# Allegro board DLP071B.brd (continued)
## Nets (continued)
SWNODE2_P2P5V: D2.1(C) L3.1 U2.41
SWNODE_CORE: D501.1(C) L6.1 Q2.3(S) U15.25
SWNODE_MOT: D6.1(C) L7.2 U15.10
SWNODE_MOT2: D3.1(C) L2.2 U2.10
SWNODE_P2P5V: D7.1(C) L9.1 U15.41
SWNODE_P3P3V: D8.1(C) L8.1 U15.43
SWNODE_P5V: D4.1(C) L5.2 U15.23
TCK: J23.9 J27.15 J42.5 R710.1 U11.N24
TDI: J23.5 J27.19 J42.2 R716.1 U11.N25
TDO1: J42.4 U11.N23
TDO2: J23.13 J27.11 R708.1 U11.N22
TILT_X: R514.2 U3.5
TILT_Y: R14.2 U3.2
TMS1: J42.3 U11.P25
TMS2: J23.7 J27.17 R715.1 U11.P26
TRACECLK: J27.6 RN504.12
TRACECLKR: RN504.5 U11.D7
TRACEPKT0: J27.30 J28.1 R641.2 RN505.9
TRACEPKT0R: RN505.8 U11.C2
TRACEPKT1: J27.28 J28.2 R640.2 RN505.10
TRACEPKT1R: RN505.7 U11.D3
TRACEPKT2: J27.26 J28.3 R639.2 RN505.11
TRACEPKT2R: RN505.6 U11.E6
TRACEPKT3: J27.24 J28.4 R638.2 RN505.12
TRACEPKT3R: RN505.5 U11.D5
TRACEPKT4: J27.22 J28.5 R637.2 RN505.13
TRACEPKT4R: RN505.4 U11.E7
TRACEPKT5: J27.20 J28.6 RN505.14
TRACEPKT5R: RN505.3 U11.C4
TRACEPKT6: J27.18 J28.7 RN505.15
TRACEPKT6R: RN505.2 U11.B4
TRACEPKT7: J27.16 J28.8 RN505.16
TRACEPKT7R: RN505.1 U11.E8
TRACESYNC: J27.32 RN504.13
TRACESYNCR: RN504.4 U11.A5
TRSTZ: J27.21 R723.1 U11.M23 U514.4
TRSTZ_IN: J23.3 J42.1 R717.1 R724.2 U514.1
UART0_CTSZ: U6.12 U9.2
UART0_CTSZ_BUF: U9.6 U11.AE2
UART0_CTSZ_CON: J7.7 U6.13
UART0_DCD_CON: J7.1 R18.1
UART0_DSR_CON: J7.6 R18.2 R19.2
UART0_DTR_CON: J7.4 R19.1
UART0_RSTZ_CON: J7.8 U6.14
UART0_RTSZ: U10.5 U11.AD2
UART0_RTSZ_BUF: R534.2 R591.1 U6.11 U10.3
UART0_RXD: R589.1 U6.9 U9.5
UART0_RXD_BUF: U9.3 U11.AD1
UART0_RXD_CON: J7.3(TD) U6.8
UART0_TXD: U10.2 U11.AB3
UART0_TXD_BUF: R535.1 U6.10 U10.6
UART0_TXD_CON: J7.2 U6.7
UART1_CTSZ: U11.E18 U12.12
UART1_CTSZ_CON: J16.7 U12.13
UART1_DCD_CON: J16.1 R29.1
UART1_DSR_CON: J16.6 R29.2 R30.2
UART1_DTR_CON: J16.4 R30.1
UART1_RSTZ_CON: J16.8 U12.14
UART1_RTSZ: R573.2 U11.A19 U12.11
UART1_RXD: J2.92 U11.D19 U12.9
UART1_RXD_CON: J16.3(TD) U12.8
UART1_TXD: J2.53 R34.1 U11.C19 U12.10
UART1_TXD_CON: J16.2 U12.7
USB_DAT_N: J4.2 R518.1 U502.6
USB_DAT_NS: DN504.1 R518.2 U11.C5
USB_DAT_P: J4.3 R519.1 R531.1 U502.1
USB_DAT_PS: DN504.2 R519.2 U11.D6
USB_ENZ: R530.1 U11.E25 U503.1
XTAL_IN: C532.1 R556.1 R557.2 U11.M26 X500.1
XTAL_OUT: R555.2 R556.2 U11.N26
N16773791: J2.1 R2.2
N16781966: J1.92 R9.2 R10.2
N16804199: D11.2(CATHODE) R699.1
N16826457: Q4.3 R699.2
N16826574: Q3.3 Q4.2 R691.2
N16826732: Q503.3 R711.1
N16826745: Q3.2 R692.2
N16826772: J17.1 R607.2
N16826808: C36.2 Q5.1 R45.1 R711.2
N16827011: C531.1 R555.1 X500.2
N16827097: Q503.2 R574.2
N16827292: R650.1 U15.1
N16827323: R46.2 R60.1 U17.4
N16827429: D9.1 R700.2
N16827460: R47.2 U17.1
N16827499: D11.1 R701.2
N16827743: D10.1 R48.2
N16830133: R666.1 R667.1 U509.1 U509.3 U509.11
N16830205: C634.1 R660.1 R661.2 U15.30 U509.4
N16830232: Q2.2 Q2.4 R611.1 U15.28
N16830236: D5.2 L6.2
N16830344: C642.2 C643.2 Q505.3(S) R659.2 R662.2 R702.2
N16830356: R616.1 U507.6
N16830372: D5.1(K) R35.1
N16830397: R617.2 U507.5
N16830529: R614.1 R615.1 U507.1 U507.2 U507.3
N16830564: R664.1 U509.6
N16830576: C642.1 R652.2 R659.1 U15.32 U509.14(W3)
N16830606: Q505.1 U15.33
N16830689: R662.1 U509.12
N16830707: R663.2 U509.13
N16830891: R665.2 U509.5
N16832566: C26.2 L7.1 R33.1
N16836092: C669.2 J59.1 L505.1 R749.1 R770.2
N16836211: R751.2 TP62.1 U519.3 VR2.2(WIPER)
N16862598: J48.3 R776.2 R777.2
N16862628: Q504.2 R668.1
N16862652: R622.2 U508.4
N16862691: R778.2 U524.4
N16862716: C676.2 R765.2 R766.2 U524.5(VCC)
N16862889: C612.2 R618.2 R620.2 U508.5(VCC)
N16862891: J34.2 Q504.3 R669.2
N16869658: J5.1 R1.2 U4.1
N16869662: R11.2 U4.55 U4.56
N16888382: J47.1 J47.8 R726.1
N16888389: J47.13 R742.1
N16888395: J47.11 R725.1
N16888418: J47.12 R741.1
N16906032: C25.1 U12.2
N16906053: C24.1 U12.6
N16906057: C546.2 U12.1
N16906061: C546.1 U12.3
N16906093: C545.2 U12.4
N16906098: C545.1 U12.5
N16906262: R532.1 R533.1 U6.16(VCC) U9.8(VCC) U10.8(VCC)
N16906414: R39.2 R40.2 R619.2 R621.2 R625.2 TP48.1
N16906499: C8.1 U6.2
N16906505: J4.1 R529.2 U503.2
N16906696: C7.1 U6.6
N16906819: C514.2 U6.1
N16906911: C514.1 U6.3
N16906913: R531.2 U503.4
N16907106: C507.2 U6.4
N16907207: C507.1 U6.5
N16910878: R586.2 U14.53
N16910921: R683.1 R684.2 U14.16(WP#/ACC)
N16911179: R584.2 U14.29
N16911537: R681.2 U14.27
N16912987: R682.2 U14.17
N16969756: R74.2 R506.1 R507.1 R508.2
N16973926: C516.2 C517.2 R520.2 U5.5(VDD2) U5.8
N16985744: R648.1 U2.1
N17028370: R53.1 U515.23
N17028379: R49.1 U515.22
N17028388: R54.1 U515.21
N17028397: R50.1 U515.20
N17028406: R55.1 U515.19
N17028415: R51.1 U515.18
N17028424: R52.1 U515.17
N17028433: R63.1 U515.16
N17028442: R62.1 U515.15(Y9)
N17028451: R64.1 U515.11
N17035653: C668.2 J60.1 L504.1 R748.1 R769.2
N17035679: C667.2 J61.1 L503.1 R747.1 R768.2
N17035705: C658.2 J37.1 L502.1 R720.1 R734.2
N17035724: C657.2 J38.1 L501.1 R719.1 R733.2
N17035755: C656.2 J39.1 L500.1 R718.1 R732.2
N17036356: R753.2 TP59.1 U519.5 VR1.2(WIPER)
N17038227: J52.2 R756.1
N17038557: J53.2 R773.1
N17038579: R773.2 U520.4
N17060093: R511.1 U501.1 U501.2 U501.3 U501.11
N17060097: C510.1 R525.1 R526.2 U2.30 U501.4
N17060101: Q1.2 Q1.4 R16.1 U2.28
N17060103: D500.2 L1.2
N17060105: D500.1(K) R527.1
N17060121: R510.2 U501.5
N17060167: R509.1 U501.6
N17126992: R597.2 U11.AC10
N17126998: R598.2 U11.AF10
N17172867: R599.2 U11.AD10
N17173381: C644.2 R695.1 R705.2 TP38.1 U512.3
N17173524: C645.2 R694.1 R695.2
N17223452: C527.1 C528.1 FB500.1 FB502.1 FB503.1 FB504.1 R536.2
N17234365: C536.1 C537.1 FB501.1 FB505.1 FB506.1 R558.2
N17385870: R596.2 U11.AB11
N17410797: C522.2 Q500.3(S) R524.2 R551.2
N17410821: Q500.1 U2.33
N17410829: R523.2 R524.1 U2.32
N17418086: J41.3 U517.22 U523.2
N17418532: J33.10 U517.16
N17418535: J33.11 U517.15(Y9)
N17423586: J41.1 R740.1 U523.4
N17451899: R736.2 SW1.1
N17529082: Q507.2 R767.2
N17529223: Q506.1 Q507.3 R746.1
N17529899: C666.2 J62.1 Q506.3
N18108465: R738.2 U513.2
N18206464: R758.1 U516.18
N18206467: R738.1 U516.17
N18206470: R759.1 U516.16
N18206473: R761.1 U516.15
N18206476: R739.1 U516.14
N18206999: J44.1 U513.4
N18269038: C16.2 U7.3(VREG5)
N18269088: C17.1 R21.2 R516.1 U7.2 U501.14(W3)
N18269114: R521.1 U501.12
N18269160: C17.2 C22.2 C23.2 L4.2 R17.1 R21.1 R26.1
N18269218: R17.2 U501.13
N18269262: C523.1 Q502.2 R23.1
N18269320: Q501.2 Q502.3 R22.1
N18269375: C21.1 L4.1 U7.6
N18374429: C21.2 U7.7

Pads without a net: J1 1 3 13 14 15 16 17 18 19 20 21 22 23 24 25 26 27 28 29 30 31 32 33 34 35 36 37 38 39 40 41 42 43 44 45 46 47 48 49 50 51 52 53 54 55 56 57 58 59 60 61 63 64 65 67 68 69 71 72 73 75 76 77 78 79 80 81 83 84 85 86 87 88 89 90 91 93 95 106 107 108 109 110 111 112 113 114 116 118 119 120; J2 3 48 106 107 109 110 111 112 120; J7 9; J14 3; J15 3; J16 9; J23 17 19; J27 1 2 3 4 7 8 10 23 25 27 29 31 33 35 37; J30 2; J54 12; J62 2; J63 B01 B20 B21 B40 C10 C11 C14 C15 C18 C19 C30 C31 C34 D01 D04 D05 D08 D09 D11 D12 D14 D15 D17 D18 D29 D30 D31 D32 D33 D34 D35 D36 D40 E02 E03 E06 E07 E09 E10 E12 E13 E15 E16 E18 E19 E33 E34 E36 E37 E39 F01 F04 F05 F07 F08 F10 F11 F13 F14 F16 F17 F19 F20 F37 F38 F40 G02 G03 G06 G07 G09 G10 G12 G13 G15 G16 G18 G19 G39 H01 H02 H04 H05 H07 H08 H10 H11 H13 H14 H16 H17 H19 H20 H40 J06 J07 J09 J10 J12 J13 J15 J16 J18 J19 J21 J22 J36 J37 J39 K01 K07 K08 K10 K11 K13 K14 K16 K17 K19 K20 K22 K23 K37 K38 K40; RN504 6 7 8 9 10 11; U2 29; U3 1 6; U4 2 3 29 31 33 35 37 40 42 44 46 48 51 53 54; U5 1 4; U11 A13; U14 28 30 55; U16 1 2; U17 5 8; U18 1; U21 11 17 18; U502 3 4 5; U505 4; U506 4; U507 12 13 14; U512 5 6 7; U516 11 12 13; U523 1

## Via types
v1: diameter 0.483, hole 0.229, TOP to BOTTOM, 541 vias
v2: diameter 0.61, hole 0.305, TOP to BOTTOM, 2226 vias
v3: diameter 0.762, hole 0.356, TOP to BOTTOM, 48 vias

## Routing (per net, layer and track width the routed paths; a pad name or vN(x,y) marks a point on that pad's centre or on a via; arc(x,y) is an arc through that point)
GND: length 2012.8
  TOP w0.193: v1(85.66,68.2) 85.66,68.23 ; U11.F12 v1(85.66,74.2) ; 86.14,68.7 U11.F6
  TOP w0.203: U14.1 48.5,57.32 v2(48.28,57.1) ; J54.11 32.35,7.61 v2(32.31,7.57) ; J54.9 v2(31.35,7.67) ; J54.7 v2(30.35,7.67) ; J54.3 v2(28.35,7.67) ; J54.5 v2(29.35,7.67)
  TOP w0.254: U11.M12 v1(91.66,74.2) ; U11.M11 v1(91.66,73.2) ; U11.L12 v1(90.66,74.2) ; U11.R15 v1(95.66,78.2) ; U11.R11 v1(95.66,73.2) ; U11.T12 v1(96.66,74.2) ; U11.R13 v1(95.66,75.2) ; v2(183.9,10.46) 184.17,10.74 U21.19 ; v2(160.53,58.93) 160.88,58.57 160.88,57.66 160.75,57.53 160.75,57.5 160.7,57.43 160.67,57.35 160.67,57.35 160.64,57.32 U15.44 ; J47.14 195.51,11.94 196.16,11.28 196.16,10.68 v2(196.04,10.56) ; U2.7 163.45,113.79 v2(163.07,114.17) ; U11.R16 v1(95.66,79.2) ; J47.9 194.21,14.47 197.87,14.47 v2(197.96,14.56) ; 159.64,63.25 159.64,63.25 159.64,63.56 159.69,63.61 159.69,64.13 159.64,64.18 U15.19 ; U11.T15 v1(96.66,78.2) ; v2(50.17,80.1) 50.49,79.78 50.49,78.27 ; U4.38 73.06,102.6 73.04,102.58 73.04,102.58 72.85,102.38 72.85,102.38 72.83,102.37 72.83,102.28 72.82,102.27 72.82,101.56 72.76,101.49 72.76,101.22 v2(72.26,100.72) ; U11.R12 v1(95.66,74.2) ; v2(47.63,78.46) 47.63,78.5 47.86,78.27 48.5,78.27 ; U11.M13 v1(91.66,75.2) ; U8.1 57.21,93.74 v2(56.63,94.33) ; v2(63.92,85.63) 63.92,85.68 63.92,85.69 U8.13 ; U11.M15 v1(91.66,78.2) ; U11.M14 v1(91.66,77.2) ; U11.P16 v1(94.66,79.2) ; U4.19 73.06,111.68 73.04,111.93 72.99,111.97 72.99,112.03 72.99,112.28 v2(72.86,112.4) ; U11.T14 v1(96.66,77.2) ; U11.N13 v1(92.66,75.2) ; U11.L14 v1(90.66,77.2) ; U11.L13 v1(90.66,75.2) ; U4.8 78.56,108.93 78.18,108.55 78.18,107.62 v2(78.09,107.53) ; U4.49 78.56,102.37 v2(78.17,101.98) ; U11.P11 v1(94.66,73.2) ; U11.N12 v1(92.66,74.2) ; v2(161.8,61.47) 162.18,61.08 U15.7 ; U11.M16 v1(91.66,79.2) ; U11.L15 v1(90.66,78.2) ; v2(59.35,85.89) 59.23,86.01 59.23,86.06 58.69,86.6 U8.12 ; U11.T13 v1(96.66,75.2) ; v2(161.8,111.63) 162.29,111.15 162.29,110.34 161.91,109.97 U2.44 ; U11.R14 v1(95.66,77.2) ; 60,78.27 60,79.64 v2(59.71,79.92) ; v2(160.53,115.44) 160.91,115.83 U2.19 ; U11.P12 v1(94.66,74.2) ; J47.10 196.8,13.94 197.16,13.58 v2(197.16,13.42) ; U11.N11 v1(92.66,73.2) ; U11.N14 v1(92.66,77.2) ; U11.P13 v1(94.66,75.2) ; U11.N15 v1(92.66,78.2) ; U11.P15 v1(94.66,78.2) ; U11.P14 v1(94.66,77.2) ; U11.N16 v1(92.66,79.2)
  TOP w0.381: v2(2.41,12.83) 2.67,13.08 2.67,13.84 2.9,14.08 J33.1 ; U11.AA6 v1(101.66,68.2) ; U11.A3 v1(80.66,65.2) ; J36.4 126.21,30.2 v2(126.86,29.56) ; U11.AB17 v1(102.66,80.2) ; U11.AD17 v1(104.66,80.2) ; U11.F9 v1(85.66,71.2) ; v2(194.17,67.29) 195.12,68.25 J16.5 ; U11.AA15 v1(101.66,78.2) ; U11.D4 v1(83.66,66.2) ; v2(183.9,36.32) 184.25,35.97 C32.1 ; U11.G5 v1(86.66,67.2) ; R6.2 v2(168.47,119.32) ; U11.B17 v1(81.66,80.2) ; U11.AC17 v1(103.66,80.2) ; U11.B2 v1(81.66,64.2) ; U11.D18 v1(83.66,81.2) ; v2(72.41,42.06) 72.03,41.68 J53.3 ; v2(42.48,68.05) 42.77,68.34 U13.12 ; U11.AF17 v1(106.66,80.2) ; v1(106.66,64.2) U11.AF2 ; U5.3 184.44,109.68 v2(184.86,110.1) ; C7.2 v2(188.72,115.95) ; R60.2 v2(180.85,28.26) ; J19.16 v2(21.62,40.64) ; U11.A2 v1(80.66,64.2) ; J19.19 v2(16,35.56) ; v2(52.1,4.67) J51.4 ; v1(105.66,65.2) U11.AE3 ; U11.L23 v1(90.66,86.2) ; U11.D17 v1(83.66,80.2) ; U16.4 173.52,23.28 v2(172.66,22.42) ; J28.12 v2(59.44,46.99) ; J19.17 v2(16.07,38.1) ; U18.3 128.58,20.02 v2(128.28,19.71) ; U11.E16 v1(84.66,79.2) ; U11.L5 v1(90.66,67.2) ; U11.B3 v1(81.66,65.2) ; v2(118.98,37.32) 119.18,37.32 119.54,37.67 J25.3 ; U11.F21 v1(85.66,84.2) ; U11.E15 v1(84.66,78.2) ; U11.K26 v1(89.66,89.2) ; v1(104.66,65.2) U11.AD3 ; U11.A1 v1(80.66,63.2) ; U11.AA9 v1(101.66,71.2) ; U6.15 191.36,104.18 v2(191.83,104.65) ; v1(95.66,67.2) U11.R5 ; U3.7 v2(178.12,113.79) ; v1(103.66,66.2) U11.AC4 ; U11.E22 v1(84.66,85.2) ; J7.5 194.68,100.76 v2(194.06,100.14) ; C42.1 v2(190.3,9.09) ; U13.34 v2(33.45,67.55) ; J28.11 v2(56.39,44.45) ; U11.E17 v1(84.66,80.2) ; v2(187.39,81.28) 187.85,81.74 C24.2 ; U11.AF25 v1(106.66,88.2) ; U11.J6 v1(88.66,68.2) ; U11.AE17 v1(105.66,80.2) ; v1(98.66,68.2) U11.V6 ; v1(95.66,68.2) U11.R6 ; U11.R26 v1(95.66,89.2) ; U11.AE24 v1(105.66,87.2) ; U9.4 v2(128.85,85.93) ; v1(100.66,67.2) U11.Y5 ; v2(178.57,25.96) 178.56,25.95 178.56,25.15 179.13,24.58 U16.7 ; U11.M25 v1(91.66,88.2) ; U11.W5 v1(99.66,67.2) ; v1(91.66,68.2) U11.M6 ; v1(106.66,65.2) U11.AF3 ; U11.A26 v1(80.66,89.2) ; U11.AB14 v1(102.66,77.2) ; U11.AB15 v1(102.66,78.2) ; C33.1 v2(188.39,35.97) ; 85.66,68.23 86.14,68.7 ; v2(162.69,23.04) 162.76,23.11 163.7,23.11 163.85,23.26 J39.3 ; v2(40.03,4.6) J50.4 ; J49.4 45.44,8.76 v2(45.06,8.38) ; J28.9 v2(56.26,39.37) ; J26.3 v2(132.74,35.98) ; v2(31.17,15.57) J42.6 ; U11.AA12 v1(101.66,74.2) ; C8.2 v2(191.13,116.14) ; J27.G5 48.26,39.37 J27.5 ; J28.10 v2(59.44,41.91) ; U11.AC18 v1(103.66,81.2) ; U11.R24 v1(95.66,87.2) ; U11.A17 v1(80.66,80.2) ; J19.1 v2(16.07,58.42) ; U11.AB22 v1(102.66,85.2) ; U11.B1 v1(81.66,63.2) ; U11.D23 v1(83.66,86.2) ; v2(71.25,28.13) 70.91,28.46 J52.3 ; U11.A25 v1(80.66,88.2) ; v1(91.66,84.2) U11.M21 ; U11.M22 v1(91.66,85.2) ; U11.B18 v1(81.66,81.2) ; U11.C18 v1(82.66,81.2) ; U11.C3 v1(82.66,65.2) ; U11.K5 v1(89.66,67.2) ; v2(174.4,1.82) 174.01,2.2 J62.3 ; U11.B25 v1(81.66,88.2) ; U11.A18 v1(80.66,81.2) ; v1(103.66,68.2) U11.AC6 ; D3.2 v2(167.04,103.91) ; J19.18 22.57,38.1 v2(21.67,39) ; U11.AD18 v1(104.66,81.2) ; U11.AB16 v1(102.66,79.2) ; U11.V5 v1(98.66,67.2) ; U11.AA21 v1(101.66,84.2) ; U11.U5 v1(97.66,67.2) ; U11.AE25 v1(105.66,88.2) ; U11.J5 v1(88.66,67.2) ; U11.C24 v1(82.66,87.2) ; U11.L25 v1(90.66,88.2) ; U11.AF24 v1(106.66,87.2) ; C30.1 v2(192.66,66.23) ; C25.2 v2(193.22,81.74) ; v2(187.26,106.68) 186.5,107.44 U5.2 ; J37.3 v2(137.43,23.7) ; U11.P24 v1(94.66,87.2) ; J55.3 v2(96.92,24.53) ; v1(85.66,78.2) U11.F15 ; U11.AA18 v1(101.66,81.2) ; v2(17.11,1.43) J48.2 ; v1(102.66,67.2) U11.AB5 ; U11.AD24 v1(104.66,87.2) ; C15.1 v2(137.03,100.9) ; v1(88.66,84.2) U11.J21 ; U11.E5 v1(84.66,67.2) ; U10.4 v2(133.24,85.93) ; U20.2 v2(173.8,20.19) ; U11.AC23 v1(103.66,86.2) ; U11.A24 v1(80.66,87.2) ; J19.20 v2(26.99,35.56) ; U11.V21 v1(98.66,84.2) ; C37.1 v2(179.32,28.07) ; U11.AF26 v1(106.66,89.2) ; U11.N5 v1(92.66,67.2) ; J43.6 v2(45.77,12.59) ; U11.AF1 v1(106.66,63.2) ; U12.15 v2(191.74,68.54) ; U3.3 v2(186.75,116.33) ; U11.F18 v1(85.66,81.2)
  TOP w0.508: J63.B07 v2(79.15,14.48) J63.B06 ; J63.A17 v2(91.85,15.75) ; J63.B26 v2(104.55,14.48) ; J63.H12 v2(85.5,5.59) ; J63.B09 v2(81.69,14.48) ; v2(175.9,96.52) 175.26,95.89 U7.5 ; C39.1 119.24,26.36 119.24,27.4 v2(119.15,27.49) ; J63.B35 v2(115.98,14.48) ; J63.H03 v2(74.07,6.86) ; v2(118.1,19.93) C40.1 118.1,20.83 ; J63.A03 v2(74.07,15.75) ; MT2.1 128.3,129.5 128.24,129.45 ; MT2.1 132.63,125.25 132.63,125.24 ; MT2.1 136.94,129.5 ; C41.1 161.34,19.05 v2(160.99,19.41) ; J63.C05 v2(76.61,13.21) ; MT3.1 196.5,131.89 196.5,131.9 ; MT3.1 196.5,122.97 196.51,122.96 ; MT3.1 192.16,127.5 192.15,127.51 ; MT1.1 25.63,125.01 25.67,124.96 ; MT1.1 21.1,129.5 21.07,129.47 ; MT1.1 30.29,129.5 30.3,129.49 ; v2(40.01,108.87) 39.04,108.87 38.1,109.82 C10.2 ; J63.F33 v2(113.44,8.13) ; v2(135.48,111.96) 136.02,112.5 D1.2 ; D2.2 152.59,105.41 v2(151.01,106.99) ; J63.C12 v2(85.5,13.21) ; J63.A01 v2(71.53,14.48) ; J63.B25 v2(103.28,14.48) ; 8.07,120.01 8.06,120 MT4.1 ; D8.2 152.92,48.65 v2(152.92,47.76) ; J63.B37 v2(118.52,14.48) ; MT4.1 3.5,115.58 3.56,115.51 ; MT4.1 3.5,124.51 3.49,124.53 ; J63.A08 v2(81.69,15.75) J63.A09 ; J63.A07 v2(79.15,15.75) ; J63.B27 v2(105.82,14.48) ; J63.F24 v2(102.01,9.4) ; U19.3 167.5,16.56 v2(167.83,16.24) ; J63.F39 v2(121.06,8.13) ; J63.K02 v2(72.8,3.05) ; C29.1 v2(167.06,66.56) ; J63.K15 v2(89.31,3.05) ; J63.G17 v2(91.85,6.86) ; J63.D06 v2(77.88,11.94) ; J63.B39 v2(121.06,14.48) ; v2(117.14,18.5) 116.99,18.66 C35.1 ; J63.D07 v2(79.15,11.94) ; J63.J29 v2(108.36,4.32) ; J63.F09 v2(81.69,8.13) ; J63.H39 v2(121.06,5.59) ; R44.2 90.84,20.22 v2(90.44,20.63) ; J63.H06 v2(77.88,5.59) ; v2(84.38,116.6) 84.77,116.99 J2.G1 88.3,116.99 v2(88.33,116.97) 88.35,116.99 J2.G2 94.39,116.99 94.44,117.04 95.4,117.04 95.43,117.02 95.56,117.02 95.59,116.99 J2.G3 100.94,116.99 v2(100.97,116.97) 101.2,116.97 101.38,116.79 102.22,116.79 102.42,116.99 J2.G4 J2.G5 108.31,116.99 108.33,116.97 108.36,116.99 J2.G6 114.66,116.99 v2(114.68,116.97) 114.71,116.99 J2.G7 120.94,116.99 v2(120.97,116.97) 120.99,116.99 J2.G8 124.87,116.99 v2(125.04,117.16) ; v2(88.44,109.1) 88.44,109.17 88.75,109.48 88.75,110.02 ; J63.D39 v2(121.06,11.94) ; C5.2 90.66,124.16 v2(91.03,124.52) 90.21,125.34 89.52,125.34 88.77,124.59 C4.2 ; J63.A27 v2(105.82,15.75) ; J63.C33 v2(113.44,13.21) ; J63.E17 v2(93.12,10.67) ; J63.K03 v2(74.07,3.05) ; J63.H30 v2(109.63,5.59) ; J57.3 108.22,24.43 v2(107.95,24.7) ; J63.A16 v2(90.58,15.75) ; J63.J32 v2(112.17,4.32) ; J38.3 150.87,23.7 v2(150.54,23.37) ; J63.E14 v2(89.31,9.4) ; v2(94.99,30.85) 95,30.84 95,30.23 94.6,29.83 VR1.1 ; C34.1 v2(115.02,19.7) ; J63.G05 v2(76.61,6.86) ; J63.E29 v2(108.36,10.67) ; J63.F06 v2(77.88,8.13) ; J63.K09 v2(81.69,3.05) ; 86.21,110.02 v2(86.21,109.13) ; J63.K33 v2(113.44,3.05) ; C11.2 v2(40.19,109.97) ; J63.G26 v2(104.55,8.13) ; J63.B31 v2(110.9,14.48) J63.A32 ; J63.D28 v2(107.09,11.94) ; J63.B29 v2(108.36,14.48) ; J63.E23 v2(100.74,10.67) ; J63.E38 v2(119.79,10.67) ; C16.1 173.99,103.76 v2(173.69,104.06) ; J63.G14 v2(88.04,6.86) ; J63.C17 v2(93.12,13.21) J63.B17 v2(93.12,14.48) J63.B18 ; J63.J20 v2(95.66,4.32) ; J63.B05 v2(76.61,14.48) ; J59.3 139.72,3.18 138.87,2.33 v2(138.87,2.29) ; J63.D13 v2(88.04,11.94) ; J63.D16 v2(91.85,10.67) ; J63.G35 v2(115.98,6.86) ; J63.B22 v2(99.47,14.48) ; C9.2 v2(35.67,109.97) ; v2(168.96,49.08) 169.92,49.08 Q3.1 ; J63.C29 v2(108.36,13.21) ; J63.A29 v2(108.36,15.75) ; C3.2 v2(38.73,124.52) ; J63.C07 v2(79.15,13.21) ; J63.F15 v2(89.31,8.13) ; C26.1 164.85,72.31 163.97,73.18 v2(163.97,73.78) ; J63.A25 v2(103.28,15.75) ; J63.A36 v2(117.25,15.75) ; 191.89,3.14 192.25,3.5 MT6.1 196.5,7.91 196.62,8.03 ; J63.E20 v2(95.66,10.67) ; J63.A04 v2(76.61,15.75) J63.A05 ; J17.5 182.28,57.35 v2(181.36,57.35) ; J63.A39 v2(121.06,15.75) ; J63.D19 v2(95.66,11.94) ; J63.H09 v2(81.69,5.59) ; J63.G29 v2(108.36,6.86) ; J63.A21 v2(98.2,15.75) ; D6.2 v2(169.56,51.21) ; J63.A37 v2(118.52,15.75) ; v2(87.46,109.12) 87.48,109.12 87.48,110.02 ; J63.C40 v2(122.33,13.21) ; J63.A12 v2(85.5,15.75) ; v2(118.08,33.66) 118.2,33.54 VR2.1 ; J63.J35 v2(115.98,4.32) ; J63.E11 v2(84.23,10.67) ; J63.K36 v2(117.25,3.05) ; Q4.1 175.14,46.23 v2(174.32,46.23) ; J63.C28 v2(107.09,13.21) ; J63.E04 v2(75.34,10.67) ; J63.B33 v2(113.44,14.48) J63.A33 ; J63.G20 v2(96.93,8.13) ; C1.1 166.12,124.08 166.75,123.44 v2(166.75,122.3) ; C2.2 v2(37.47,124.52) ; J63.K24 v2(100.74,3.05) ; J63.D37 v2(118.52,11.94) ; C18.1 171.81,97.33 ; J63.C03 v2(74.07,13.21) ; J63.G01 v2(71.53,6.86) ; J63.C25 v2(103.28,13.21) ; J63.J01 v2(71.53,4.32) ; 3.91,8.06 3.5,7.65 MT5.1 7.56,3.5 7.99,3.94 ; J63.B30 v2(109.63,14.48) J63.A31 ; J63.G32 v2(112.17,6.86) ; J63.F36 v2(117.25,8.13) ; J63.A35 v2(115.98,15.75) ; v2(162.5,2.16) 163.22,2.88 J61.3 ; J63.F12 v2(86.77,8.13) ; J63.A11 v2(84.23,15.75) ; J63.C13 v2(86.77,13.21) ; J63.B15 v2(90.58,14.48) ; v2(150.81,2.29) 151.79,3.26 J60.3 ; J63.C20 v2(96.93,13.21) ; J63.C08 v2(80.42,13.21) ; v2(33.34,116.97) 33.36,116.99 J1.G1 37.25,116.99 v2(37.27,116.97) 37.3,116.99 J1.G2 43.47,116.99 v2(43.5,116.97) 43.52,116.99 J1.G3 49.82,116.99 v2(49.85,116.97) 49.87,116.99 J1.G4 J1.G5 57.19,116.99 v2(57.21,116.97) 57.24,116.99 J1.G6 63.53,116.99 v2(63.56,117.03) 63.6,116.99 J1.G7 69.88,116.99 v2(69.91,117.03) 69.95,116.99 J1.G8 73.89,116.99 v2(73.91,116.97) ; J63.C04 v2(75.34,13.21) ; J63.D22 v2(99.47,11.94) ; J63.F27 v2(105.82,9.4) ; J63.A28 v2(107.09,15.75) ; J63.J14 v2(89.31,5.59) ; C38.1 v2(26.37,26.99) ; J63.A40 v2(122.33,15.75) ; J63.K12 v2(85.5,3.05) ; J63.E01 v2(71.53,10.67) ; J63.C21 v2(98.2,13.21) ; J63.B38 v2(119.79,14.48) ; J63.H36 v2(117.25,5.59) ; J63.H15 v2(90.58,5.59) ; J63.C01 v2(71.53,13.21) ; J63.B10 v2(82.96,14.48) ; J63.K18 v2(93.12,3.05) ; J63.J26 v2(104.55,4.32) ; J63.C09 v2(81.69,13.21) ; J63.G04 v2(75.34,6.86) ; J63.H33 v2(113.44,5.59) ; J63.J40 v2(122.33,4.32) ; J63.B14 v2(89.31,14.48) ; J63.H21 v2(96.93,5.59) ; J63.J05 v2(76.61,4.32) ; J63.F02 v2(72.8,9.4) ; J63.J23 v2(100.74,4.32) ; C31.1 v2(135.57,48.56) ; J63.J04 v2(75.34,4.32) ; J63.A13 v2(86.77,15.75) ; J63.G11 v2(84.23,6.86) ; C27.1 v2(152.02,67.82) ; J63.H24 v2(100.74,5.59) ; J63.B23 v2(100.74,14.48) ; J63.E40 v2(122.33,10.67) ; J63.G38 v2(119.79,6.86) ; J63.D03 v2(74.07,11.94) ; J63.E35 v2(115.98,10.67) ; J63.F18 v2(93.12,8.13) ; J63.B11 v2(84.23,14.48) ; v2(106.07,40.72) 106.72,40.07 J24.5 ; J63.J38 v2(119.79,4.32) ; D7.2 142.65,46.33 v2(143.38,45.59) ; J63.K06 v2(77.88,3.05) ; J63.F03 v2(74.07,9.4) ; J63.C36 v2(117.25,13.21) ; J63.A15 v2(89.31,15.75) ; J63.J11 v2(84.23,4.32) ; D9.2 174.21,40.12 v2(174.12,40.21) ; J63.D25 v2(103.28,11.94) ; J63.A20 v2(95.66,15.75) ; J63.G40 v2(122.33,6.86) ; J63.A23 v2(100.74,15.75) ; J63.G23 v2(100.74,8.13) ; J63.J17 v2(91.85,4.32) ; v2(187.34,30.16) 187.34,30.16 D10.2 ; J63.C32 v2(112.17,13.21) ; J63.E05 v2(76.61,10.67) ; J63.C16 v2(91.85,11.94) ; J63.H18 v2(94.39,5.59) ; J63.A19 v2(94.39,15.75) ; J63.K30 v2(109.63,3.05) ; J63.D10 v2(82.96,11.94) ; J63.F21 v2(98.2,9.4) ; J63.B13 v2(86.77,14.48) ; J63.G08 v2(80.42,6.86) ; J63.B03 v2(74.07,14.48) ; J63.K21 v2(98.2,3.05) ; J63.E32 v2(112.17,10.67) ; J63.H27 v2(104.55,6.86) ; J63.C38 v2(119.79,13.21) ; R31.2 v2(166.69,69.67) ; J63.C24 v2(102.01,13.21) ; J63.B19 v2(94.39,14.48) ; J63.E08 v2(80.42,10.67) ; J63.B34 v2(114.71,14.48) ; J63.E26 v2(104.55,10.67) ; J63.J08 v2(80.42,4.32) ; J63.B02 v2(72.8,14.48) ; J63.K27 v2(105.82,3.05) ; J63.D02 v2(72.8,11.94) ; J63.F30 v2(109.63,8.13) ; J63.K39 v2(121.06,3.05) ; J63.A24 v2(102.01,15.75) ; J30.3 v2(136.23,32.45)
  L02_GND1 w0.508: 33.43,46.13 J23.18 ; J23.18 33.43,47.85 ; J23.18 35.15,47.85 ; J23.18 35.15,46.13 ; 193.32,26.85 J32.5 ; J32.5 194.95,26.85 ; J32.5 193.32,25.22 ; J32.5 194.95,25.22 ; 20.47,13.59 21.58,13.59 J35.14 22.86,13.6 22.92,13.54 24.27,13.54 ; 7.46,51.31 J18.7 ; J18.7 9.05,51.31 ; J18.7 7.46,49.72 ; J18.7 9.05,49.72 ; J27.G1 49.66,29.08 ; J27.G1 48.13,29.08 ; J27.G1 48.13,30.61 ; J27.G1 49.66,30.61 ; 33.43,41.05 J23.14 ; J23.14 33.43,42.77 ; J23.14 35.15,41.05 ; J23.14 35.15,42.77 ; J22.GND2 191.33,52.05 ; J22.GND2 191.33,49.99 ; J22.GND2 187.26,52.05 ; J22.GND2 187.26,49.99 ; J45.2 71.6,21.78 ; J45.2 71.6,23.5 ; J45.2 69.88,23.5 ; J45.2 69.88,21.78 ; 24.24,14.81 22.9,14.81 22.86,14.85 J35.13 21.53,14.91 20.37,14.91 ; J23.8 35.15,33.43 ; J23.8 33.43,33.43 ; J23.8 33.43,35.15 ; J23.8 35.15,35.15 ; 36.38,106.46 J5.2 ; J5.2 38.1,106.46 ; J5.2 36.38,108.17 ; J5.2 38.1,108.17 ; 185.42,12.69 v2(185.42,13.65) ; 185.42,12.69 185.35,12.61 ; 185.42,12.69 185.47,12.73 ; v2(185.42,13.65) 185.42,14.67 185.46,14.71 ; v2(185.42,13.65) 184.35,13.65 184.31,13.69 ; v2(185.42,13.65) 186.59,13.65 186.63,13.61 ; 193.32,32.84 J32.7 ; J32.7 194.95,32.84 ; J32.7 193.32,31.21 ; J32.7 194.95,31.21 ; J18.16 7.05,43.31 ; J18.16 7.05,41.72 ; J18.16 5.46,41.72 ; J18.16 5.46,43.31 ; U7.9 178.93,97.3 ; U7.9 178.93,98.28 ; U7.9 177.94,97.3 ; U7.9 177.94,98.28 ; 48.13,35.69 J27.G3 ; J27.G3 49.66,35.69 ; J27.G3 48.13,34.16 ; J27.G3 49.66,34.16 ; 48.13,39.24 J27.G5 ; J27.G5 49.66,39.24 ; J27.G5 49.66,40.77 ; J27.G5 48.13,40.77 ; 46.77,99.38 J8.2 ; J8.2 46.77,97.66 ; J8.2 48.48,97.66 ; J8.2 48.48,99.38 ; J22.GND1 193.33,44.29 ; J22.GND1 191.26,48.35 ; J22.GND1 191.26,44.29 ; J22.GND1 193.33,48.35 ; J15.5 9.16,75.49 ; J15.5 7.35,75.49 ; J15.5 9.16,73.68 ; J15.5 7.35,73.68 ; 48.13,33.15 J27.G2 ; J27.G2 49.66,33.15 ; J27.G2 49.66,31.62 ; J27.G2 48.13,31.62 ; 185.22,5.28 U22.2 ; U22.2 186.89,5.28 ; U22.2 185.22,3.61 ; U22.2 186.89,3.61 ; 33.43,37.69 J23.10 ; J23.10 33.43,35.97 ; J23.10 35.15,35.97 ; J23.10 35.15,37.69 ; J23.20 35.15,50.39 ; J23.20 35.15,48.67 ; J23.20 33.43,50.39 ; J23.20 33.43,48.67 ; 14.41,121.99 U1.2 ; U1.2 14.41,120.33 ; U1.2 16.07,121.99 ; U1.2 16.07,120.33 ; 196.1,122.05 196.5,122.45 MT3.1 188.34,127.5 188.25,127.58 ; 163.52,54.36 TP36.1 ; TP36.1 164.34,53.21 164.37,53.17 ; TP36.1 164.34,55.51 164.55,55.72 ; TP36.1 166.55,54.36 166.81,54.1 ; J23.12 35.15,40.23 ; J23.12 35.15,38.51 ; J23.12 33.43,40.23 ; J23.12 33.43,38.51 ; J6.2 43.18,108.17 ; J6.2 43.18,106.46 ; J6.2 41.46,108.17 ; J6.2 41.46,106.46 ; 3.52,9.4 3.5,9.38 MT5.1 8.57,3.5 8.65,3.58 ; J4.4 13.77,105.27 ; J4.4 12.21,106.82 ; J4.4 12.21,105.27 ; J4.4 13.77,106.82 ; 185.82,13.25 U21.25 ; U21.25 186.8,13.25 ; U21.25 186.8,12.27 ; U21.25 185.82,12.27 ; 190.32,31.21 J32.3 ; J32.3 190.32,32.84 ; J32.3 191.95,32.84 ; J32.3 191.95,31.21 ; 190.89,3.51 190.9,3.5 MT6.1 196.5,9.15 196.33,9.32 ; J23.6 35.15,32.61 ; J23.6 33.43,30.89 ; J23.6 35.15,30.89 ; J23.6 33.43,32.61 ; J18.15 9.05,43.31 ; J18.15 9.05,41.72 ; J18.15 7.46,41.72 ; J18.15 7.46,43.31 ; J20.2 50.48,49.31 ; J20.2 48.77,49.31 ; J20.2 50.48,51.02 ; J20.2 48.77,51.02 ; 65.85,98.5 65.87,98.52 66.99,98.52 ; J32.1 191.95,26.85 ; J32.1 191.95,25.22 ; J32.1 190.32,25.22 ; J32.1 190.32,26.85 ; 66.99,98.52 68.45,98.52 68.47,98.5 ; 66.99,98.52 66.99,98.88 66.23,99.64 ; J23.4 35.15,28.35 ; J23.4 33.43,28.35 ; J23.4 35.15,30.07 ; J23.4 33.43,30.07 ; J27.G4 49.66,36.7 ; J27.G4 48.13,38.23 ; J27.G4 48.13,36.7 ; J27.G4 49.66,38.23 ; 33.43,43.59 J23.16 ; J23.16 35.15,45.31 ; J23.16 35.15,43.59 ; J23.16 33.43,45.31 ; J18.10 7.05,49.31 ; J18.10 5.46,49.31 ; J18.10 7.05,47.72 ; J18.10 5.46,47.72 ; 3.11,77.49 J14.5 ; J14.5 4.92,77.49 ; J14.5 3.11,75.68 ; J14.5 4.92,75.68
  L02_GND1 w1.27: 19.63,129.53 25.59,129.53 MT1.1 ; 31.07,129.63 30.94,129.5 MT1.1 ; MT4.1 3.51,120.01 8.06,120.01 ; MT4.1 3.45,120.05 3.45,125.04 ; MT4.1 3.35,119.85 3.35,115.77 ; MT1.1 25.63,124.27 25.48,124.12 ; 132.5,124.64 132.63,124.76 MT2.1 ; 127.45,129.37 127.57,129.5 MT2.1 ; 138.34,129.51 138.32,129.5 MT2.1
  L03_SIG1 w0.508: 1.51,8.09 3.5,6.11 MT5.1 7.79,3.5 7.91,3.63 ; MT2.1 132.63,125.19 132.62,125.19 ; MT2.1 128.28,129.5 128.26,129.52 ; MT2.1 136.97,129.5 136.98,129.49 ; 192.02,127.49 192.03,127.5 MT3.1 196.5,122.34 196.49,122.33 ; 30.31,129.33 30.14,129.5 MT1.1 ; 25.7,124.79 25.63,124.86 MT1.1 ; 8.08,120.02 8.07,120 MT4.1 ; MT4.1 3.5,115.65 3.61,115.53 ; MT4.1 3.5,124.5 3.52,124.52 ; MT1.1 20.5,129.5 20.31,129.69
  L04_GND2 w0.508: 69.88,23.5 J45.2 ; J45.2 71.6,23.5 ; J45.2 69.88,21.78 ; J45.2 71.6,21.78 ; 33.43,30.07 J23.4 ; J23.4 35.15,30.07 ; J23.4 35.15,28.35 ; J23.4 33.43,28.35 ; J18.7 9.05,49.72 ; J18.7 7.46,51.31 ; J18.7 9.05,51.31 ; J18.7 7.46,49.72 ; 33.43,32.61 J23.6 ; J23.6 33.43,30.89 ; J23.6 35.15,30.89 ; J23.6 35.15,32.61 ; 12.21,106.82 J4.4 ; J4.4 13.77,105.27 ; J4.4 13.77,106.82 ; J4.4 12.21,105.27 ; 48.77,49.31 J20.2 ; J20.2 50.48,49.31 ; J20.2 50.48,51.02 ; J20.2 48.77,51.02 ; J32.7 194.95,32.84 ; J32.7 193.32,31.21 ; J32.7 194.95,31.21 ; J32.7 193.32,32.84 ; 187.26,49.99 J22.GND2 ; J22.GND2 191.33,49.99 ; J22.GND2 191.33,52.05 ; J22.GND2 187.26,52.05 ; 14.41,120.33 U1.2 ; U1.2 16.07,120.33 ; U1.2 14.41,121.99 ; U1.2 16.07,121.99 ; J8.2 48.48,97.66 ; J8.2 46.77,99.38 ; J8.2 48.48,99.38 ; J8.2 46.77,97.66 ; J5.2 38.1,108.17 ; J5.2 36.38,108.17 ; J5.2 38.1,106.46 ; J5.2 36.38,106.46 ; 33.43,35.97 J23.10 ; J23.10 35.15,35.97 ; J23.10 35.15,37.69 ; J23.10 33.43,37.69 ; 185.82,13.25 U21.25 ; U21.25 186.8,13.25 ; U21.25 186.8,12.27 ; U21.25 185.82,12.27 ; J23.20 35.15,48.67 ; J23.20 35.15,50.39 ; J23.20 33.43,50.39 ; J23.20 33.43,48.67 ; 48.13,38.23 J27.G4 ; J27.G4 48.13,36.7 ; J27.G4 49.66,36.7 ; J27.G4 49.66,38.23 ; J14.5 4.92,77.49 ; J14.5 3.11,75.68 ; J14.5 4.92,75.68 ; J14.5 3.11,77.49 ; J23.12 35.15,38.51 ; J23.12 33.43,38.51 ; J23.12 33.43,40.23 ; J23.12 35.15,40.23 ; 48.13,40.77 J27.G5 ; J27.G5 49.66,40.77 ; J27.G5 48.13,39.24 ; J27.G5 49.66,39.24 ; J27.G3 49.66,34.16 ; J27.G3 48.13,34.16 ; J27.G3 49.66,35.69 ; J27.G3 48.13,35.69 ; J18.15 9.05,41.72 ; J18.15 7.46,43.31 ; J18.15 7.46,41.72 ; J18.15 9.05,43.31 ; 190.32,31.21 J32.3 ; J32.3 190.32,32.84 ; J32.3 191.95,31.21 ; J32.3 191.95,32.84 ; U22.2 186.89,5.28 ; U22.2 186.89,3.61 ; U22.2 185.22,5.28 ; U22.2 185.22,3.61 ; J18.16 7.05,43.31 ; J18.16 5.46,43.31 ; J18.16 7.05,41.72 ; J18.16 5.46,41.72 ; 188.25,127.58 188.34,127.5 MT3.1 196.5,122.45 196.1,122.05 ; U7.9 178.93,97.3 ; U7.9 177.94,97.3 ; U7.9 177.94,98.28 ; U7.9 178.93,98.28 ; 5.46,47.72 J18.10 ; J18.10 7.05,49.31 ; J18.10 7.05,47.72 ; J18.10 5.46,49.31 ; 7.35,73.68 J15.5 ; J15.5 7.35,75.49 ; J15.5 9.16,75.49 ; J15.5 9.16,73.68 ; J6.2 43.18,108.17 ; J6.2 41.46,108.17 ; J6.2 41.46,106.46 ; J6.2 43.18,106.46 ; 33.43,42.77 J23.14 ; J23.14 33.43,41.05 ; J23.14 35.15,42.77 ; J23.14 35.15,41.05 ; 191.26,44.29 J22.GND1 ; J22.GND1 191.26,48.35 ; J22.GND1 193.33,48.35 ; J22.GND1 193.33,44.29 ; 33.43,46.13 J23.18 ; J23.18 35.15,47.85 ; J23.18 33.43,47.85 ; J23.18 35.15,46.13 ; 48.13,30.61 J27.G1 ; J27.G1 49.66,30.61 ; J27.G1 49.66,29.08 ; J27.G1 48.13,29.08 ; J27.G2 49.66,31.62 ; J27.G2 48.13,31.62 ; J27.G2 48.13,33.15 ; J27.G2 49.66,33.15 ; 190.89,3.51 190.9,3.5 MT6.1 196.5,9.15 196.33,9.32 ; J23.8 35.15,35.15 ; J23.8 33.43,33.43 ; J23.8 35.15,33.43 ; J23.8 33.43,35.15 ; J32.5 194.95,25.22 ; J32.5 193.32,26.85 ; J32.5 193.32,25.22 ; J32.5 194.95,26.85 ; 3.52,9.4 3.5,9.38 MT5.1 8.57,3.5 8.65,3.58 ; 190.32,26.85 J32.1 ; J32.1 191.95,25.22 ; J32.1 190.32,25.22 ; J32.1 191.95,26.85 ; J23.16 35.15,45.31 ; J23.16 33.43,43.59 ; J23.16 35.15,43.59 ; J23.16 33.43,45.31
  L04_GND2 w1.27: MT2.1 127.57,129.5 127.45,129.37 ; MT2.1 132.63,124.76 132.5,124.64 ; MT2.1 138.32,129.5 138.34,129.51 ; 3.35,115.77 3.35,119.85 MT4.1 ; MT4.1 3.45,120.05 3.45,125.04 ; MT4.1 3.51,120.01 8.06,120.01 ; 25.48,124.12 25.63,124.27 MT1.1 ; 31.07,129.63 30.94,129.5 MT1.1 ; MT1.1 25.59,129.53 19.63,129.53
  L05_SIG2 w0.508: 30.21,129.64 30.07,129.5 MT1.1 ; MT1.1 25.63,129.05 22.38,125.8 ; MT1.1 20.43,129.5 20.38,129.55 ; 191.58,3.05 192.02,3.5 MT6.1 196.5,7.49 196.94,7.93 ; 3.45,115.52 3.5,115.58 MT4.1 ; 128.22,129.09 128.63,129.5 MT2.1 136.44,129.5 136.92,129.98 ; MT4.1 7.81,120 8.23,119.58 ; MT4.1 3.5,124.12 4,124.62 ; 196.97,122.56 196.5,123.03 MT3.1 196.5,131.47 196.06,131.91 ; 7.91,3.88 7.54,3.5 MT5.1 3.5,6.86 2.48,7.89
  L06_GND3 w0.508: 33.43,37.69 J23.10 ; J23.10 35.15,37.69 ; J23.10 35.15,35.97 ; J23.10 33.43,35.97 ; J27.G1 49.66,29.08 ; J27.G1 49.66,30.61 ; J27.G1 48.13,29.08 ; J27.G1 48.13,30.61 ; U22.2 186.89,3.61 ; U22.2 185.22,5.28 ; U22.2 185.22,3.61 ; U22.2 186.89,5.28 ; 8.65,3.58 8.57,3.5 MT5.1 3.5,9.38 3.52,9.4 ; 190.32,31.21 J32.3 ; J32.3 190.32,32.84 ; J32.3 191.95,31.21 ; J32.3 191.95,32.84 ; 33.43,48.67 J23.20 ; J23.20 35.15,48.67 ; J23.20 33.43,50.39 ; J23.20 35.15,50.39 ; 12.21,105.27 J4.4 ; J4.4 13.77,106.82 ; J4.4 13.77,105.27 ; J4.4 12.21,106.82 ; J32.1 191.95,25.22 ; J32.1 190.32,25.22 ; J32.1 191.95,26.85 ; J32.1 190.32,26.85 ; J18.10 7.05,49.31 ; J18.10 5.46,49.31 ; J18.10 5.46,47.72 ; J18.10 7.05,47.72 ; J22.GND2 191.33,49.99 ; J22.GND2 187.26,49.99 ; J22.GND2 187.26,52.05 ; J22.GND2 191.33,52.05 ; 41.46,108.17 J6.2 ; J6.2 43.18,106.46 ; J6.2 41.46,106.46 ; J6.2 43.18,108.17 ; J23.18 35.15,46.13 ; J23.18 35.15,47.85 ; J23.18 33.43,47.85 ; J23.18 33.43,46.13 ; 14.41,120.33 U1.2 ; U1.2 16.07,121.99 ; U1.2 16.07,120.33 ; U1.2 14.41,121.99 ; 33.43,28.35 J23.4 ; J23.4 33.43,30.07 ; J23.4 35.15,28.35 ; J23.4 35.15,30.07 ; J15.5 9.16,73.68 ; J15.5 7.35,73.68 ; J15.5 7.35,75.49 ; J15.5 9.16,75.49 ; J23.8 35.15,35.15 ; J23.8 33.43,33.43 ; J23.8 33.43,35.15 ; J23.8 35.15,33.43 ; J23.16 35.15,45.31 ; J23.16 33.43,43.59 ; J23.16 33.43,45.31 ; J23.16 35.15,43.59 ; J32.5 194.95,25.22 ; J32.5 194.95,26.85 ; J32.5 193.32,25.22 ; J32.5 193.32,26.85 ; 177.94,97.3 U7.9 ; U7.9 178.93,98.28 ; U7.9 177.94,98.28 ; U7.9 178.93,97.3 ; 48.13,38.23 J27.G4 ; J27.G4 49.66,38.23 ; J27.G4 49.66,36.7 ; J27.G4 48.13,36.7 ; 48.13,31.62 J27.G2 ; J27.G2 48.13,33.15 ; J27.G2 49.66,33.15 ; J27.G2 49.66,31.62 ; 33.43,41.05 J23.14 ; J23.14 35.15,41.05 ; J23.14 35.15,42.77 ; J23.14 33.43,42.77 ; 36.38,106.46 J5.2 ; J5.2 36.38,108.17 ; J5.2 38.1,106.46 ; J5.2 38.1,108.17 ; 7.46,41.72 J18.15 ; J18.15 9.05,41.72 ; J18.15 7.46,43.31 ; J18.15 9.05,43.31 ; J18.16 7.05,43.31 ; J18.16 7.05,41.72 ; J18.16 5.46,41.72 ; J18.16 5.46,43.31 ; 69.88,23.5 J45.2 ; J45.2 71.6,21.78 ; J45.2 71.6,23.5 ; J45.2 69.88,21.78 ; J14.5 4.92,75.68 ; J14.5 3.11,77.49 ; J14.5 4.92,77.49 ; J14.5 3.11,75.68 ; 46.77,97.66 J8.2 ; J8.2 48.48,97.66 ; J8.2 48.48,99.38 ; J8.2 46.77,99.38 ; 191.26,48.35 J22.GND1 ; J22.GND1 193.33,44.29 ; J22.GND1 193.33,48.35 ; J22.GND1 191.26,44.29 ; J23.12 35.15,38.51 ; J23.12 35.15,40.23 ; J23.12 33.43,40.23 ; J23.12 33.43,38.51 ; 185.82,13.25 U21.25 ; U21.25 186.8,13.25 ; U21.25 186.8,12.27 ; U21.25 185.82,12.27 ; 7.46,51.31 J18.7 ; J18.7 7.46,49.72 ; J18.7 9.05,49.72 ; J18.7 9.05,51.31 ; J27.G5 49.66,40.77 ; J27.G5 49.66,39.24 ; J27.G5 48.13,39.24 ; J27.G5 48.13,40.77 ; 193.32,31.21 J32.7 ; J32.7 194.95,32.84 ; J32.7 193.32,32.84 ; J32.7 194.95,31.21 ; J27.G3 49.66,35.69 ; J27.G3 48.13,34.16 ; J27.G3 48.13,35.69 ; J27.G3 49.66,34.16 ; J23.6 35.15,30.89 ; J23.6 33.43,30.89 ; J23.6 33.43,32.61 ; J23.6 35.15,32.61 ; 190.89,3.51 190.9,3.5 MT6.1 196.5,9.15 196.33,9.32 ; J20.2 50.48,49.31 ; J20.2 48.77,51.02 ; J20.2 48.77,49.31 ; J20.2 50.48,51.02 ; 196.1,122.05 196.5,122.45 MT3.1 188.34,127.5 188.25,127.58
  L06_GND3 w1.27: 138.34,129.51 138.32,129.5 MT2.1 ; 8.06,120.01 3.51,120.01 MT4.1 ; MT2.1 127.57,129.5 127.45,129.37 ; MT2.1 132.63,124.76 132.5,124.64 ; MT4.1 3.45,120.05 3.45,125.04 ; MT4.1 3.35,119.85 3.35,115.77 ; 19.63,129.53 25.59,129.53 MT1.1 ; 25.48,124.12 25.63,124.27 MT1.1 ; MT1.1 30.94,129.5 31.07,129.63
  BOTTOM w0.102: v1(89.48,72.05) 89.57,72.05 89.53,72.01 v1(89.53,70.99) ; 86.66,90.83 86.69,90.81 C534.2 ; 88.76,81.41 C569.2
  BOTTOM w0.203: 2.69,16.1 2.16,16.1 v2(1.8,15.75) ; 2.69,16.1 2.74,16.15 2.74,16.51 2.99,16.75 U517.10 ; 2.69,16.1 U517.9 ; v1(90.66,86.2) 90.93,86.2 91.41,86.67 93.15,86.67 C543.2 ; U516.19 v2(47.45,17.53) ; U516.1 50.42,17.93 v2(49.99,18.36)
  BOTTOM w0.254: v2(54.9,75.68) 54.9,75.68 54.9,75.68 54.91,75.68 54.91,75.68 54.91,75.68 54.91,75.68 54.94,75.68 54.94,75.64 54.99,75.69 C573.1 ; C597.2 87.99,73.41 88.11,73.29 88.55,73.29 88.61,73.34 v1(89.09,73.34) ; v2(138.05,54.74) 138.41,54.74 138.5,54.63 139.39,54.63 139.84,55.08 139.84,55.86 139.59,56.1 U509.2 ; C600.2 87.74,69.22 C596.2 88.6,70.05 v1(89.53,70.99) ; U509.10 142.76,58.05 142.03,58.78 142.03,59.76 141.35,60.44 140.1,60.44 v2(139.66,59.99) ; v2(145.45,60.33) 144.91,60.33 144.08,59.5 U509.8 ; U507.11 142.04,62.99 v2(141.44,62.38) ; C601.2 88.27,72.39 v1(88.39,72.52) ; v1(95.72,81.53) 95.69,81.53 96.11,81.95 96.11,82.26 C561.2 ; U515.12 v2(31.73,18.11) ; v1(91.66,88.2) 92.17,88.71 92.94,88.71 93.16,88.92 93.16,89.77 C541.2 ; C599.2 C598.2 88.33,71.25 v1(88.39,71.31) ; C564.2 91,81.56 v1(91.17,81.38) ; v2(31.85,4.86) 31.74,4.75 C672.1 ; C587.2 v1(96.71,70.92) ; U507.8 144.61,64.94 144.88,65.22 145.87,65.22 146.01,65.07 v2(146.01,65.06) ; C562.2 95.19,82.35 94.93,82.09 94.93,81.66 v1(94.81,81.53) ; R744.2 v2(188.34,11.43) ; C586.2 98.11,70.92 v1(98.13,70.94) ; v1(89.9,81.36) 89.85,81.41 C566.2 89.79,82.28 C567.2 ; U501.8 176.89,113.18 v2(177.26,112.82) ; C542.2 93.79,82.14 v1(93.66,82.02) ; v2(163.07,114.17) 163.4,113.84 C512.1 ; v2(161.8,61.47) 162.13,61.14 C607.1 ; v1(99.06,80.9) 99.69,81.53 C555.2 99.81,81.6 C553.2 99.87,82.61 C540.2 ; v2(176.21,116.21) 175.59,115.59 U501.10 ; v1(95.66,73.2) 95.68,73.18 C588.2 ; C592.2 v1(92.39,70.99) ; 95.78,89.87 95.66,89.76 v1(95.66,89.2) ; C608.2 160.22,63.04 v2(160.53,62.74) ; v1(88.81,81.36) 87.74,82.42 C568.2 C544.2 ; C590.2 94.61,70.93 v1(94.6,70.94) ; v1(88.68,80.09) 88.73,80.14 C565.2 ; U515.13 24.82,18.9 v2(24.25,19.47) ; C593.2 91.64,73.18 v1(91.66,73.2) 91.66,73.2 ; v1(92.62,81.38) 92.67,81.43 C563.2 ; C558.2 98.74,81.85 v1(98.11,81.22) ; v2(142.3,63.64) 142.31,63.64 142.31,63.64 U507.10 ; C556.2 v1(98.68,78.74) ; C595.2 90.74,69.99 C594.2 v1(90.81,70.99) ; U504.3 23.7,76.39 ; U515.1 v2(31.73,27.6) ; U506.3 v2(24.13,71.63)
  BOTTOM w0.305: U517.13 v2(10.07,18.84) ; U517.12 v2(5.82,18.05) ; U517.1 v2(3.04,10.9)
  BOTTOM w0.381: C659.1 42.81,17.39 42.54,17.66 v2(42.54,19.3) ; C665.1 19.56,6.73 v2(19.18,6.35) ; C581.2 101.66,68.4 v1(101.66,68.2) ; C589.2 v1(95.69,71.05) ; C574.1 v2(193.04,74.8) ; v2(187.26,106.68) 186.89,107.05 C515.1 ; C639.2 181.79,44.14 181.3,43.64 v2(181.3,42.68) ; v2(172.66,22.42) 172.72,22.48 C653.1 ; C602.2 86.22,74.21 86.06,74.21 86.05,74.2 v1(85.66,74.2) ; C613.2 v2(114.56,68.45) ; C578.2 113.78,70.1 113.95,69.93 v2(114.64,69.93) ; R688.2 v2(53.06,51.66) ; v1(95.66,67.2) 95,66.54 C626.2 ; v2(168.17,130.33) 168.15,130.3 DN501.1 ; C652.1 v2(42.67,42.55) ; C580.2 99.81,71.06 C583.2 99.29,71.12 98.9,71.52 98.9,71.48 v1(98.9,71.48) ; C675.1 17.14,1.46 v2(17.12,1.43) ; C606.2 v2(189.29,62.87) ; U505.14 v2(184.01,74.72) ; R724.1 37.66,25.08 37.66,25.14 v2(37.69,25.14) ; v2(70.48,26.23) 70.1,26.61 C674.1 ; U522.1 18.08,7.16 18.41,7.49 18.41,7.62 v2(18.8,8) ; v1(81.66,63.2) 81.58,63.12 C628.2 ; C533.2 88.95,90.13 89.66,89.41 v1(89.66,89.2) ; U524.1 v2(11.38,9.19) ; C662.1 101.22,33.4 v2(100.9,33.72) ; v2(130.65,84.57) 130.65,84.61 130.54,84.72 C539.1 ; v2(173.8,20.19) 173.81,20.21 C655.1 ; v1(98.87,72.39) 99.62,72.39 C582.2 ; v2(42.48,68.05) 42.66,67.87 C629.1 ; U511.1 v2(44.4,50.5) ; U511.2 v2(43.12,48.58) ; C648.1 v2(140.04,42.39) ; Q503.1 v2(177.91,80) ; v2(177.61,127.44) 177.14,126.97 DN500.1 ; C651.1 122.03,39.03 122.14,39.14 v2(122.14,39.76) ; U514.2 v2(40.26,26.04) ; C618.2 114.08,60.71 v2(114.47,61.1) 114.1,61.47 C617.2 ; C673.1 v2(71.25,28.13) ; v2(110.11,24.51) 110.11,24.71 109.47,25.34 C661.1 ; R757.1 v2(65.79,24.51) ; C517.1 180.26,105.74 179.77,106.24 178.88,106.24 v2(178.63,106.49) ; C620.2 110.81,63.75 v1(110.87,63.7) ; C650.1 135.13,39.37 v2(134.75,39.75) ; v2(33.45,67.55) 33.32,67.42 C630.1 ; C571.2 88.28,78.87 v1(88.48,79.07) ; U520.1 v2(65.35,39.32) ; U510.1 40.78,43.83 v2(40.51,43.56) ; v2(14.16,7.3) 13.53,7.3 13.26,7.57 U524.3 ; C547.2 v2(181.67,76.58) ; Q507.1 171.53,4.78 170.81,4.06 v2(170.81,3.3) ; R534.1 189.1,104.39 189.33,104.62 v2(189.33,104.82) ; C516.1 181.36,106.94 v2(182.22,107.8) ; v1(85.66,78.2) 86.21,78.2 C572.2 ; C584.2 98.23,70.12 C586.2 ; C614.2 v2(114.64,66.04) 113.88,65.28 C615.2 ; v1(110.82,67.54) 110.59,67.31 R632.1 C619.2 ; C623.2 106.66,62.34 v1(106.66,63.2) ; R745.2 183.51,12.18 183.88,11.81 183.88,11.81 C660.1 184.26,10.77 183.9,10.4 v2(183.9,10.46) ; C523.2 193.19,95.33 v2(194.46,96.6) ; v2(42.79,46.74) 42.79,45.94 42.73,45.88 42.13,45.88 U510.3 ; U519.4 106.03,28.49 105.95,28.4 v2(105.95,28.49) ; Q502.1 v2(190.32,90.12) ; C616.2 v2(114.42,63.75) ; C663.1 v2(35.31,8.1) ; R764.1 21.46,6.73 v2(22.73,5.46) ; C676.1 9.13,4.08 v2(9.26,3.95) ; U521.1 v2(68.63,24.97) ; C645.1 124.14,44.7 v2(124.12,44.73) ; R683.2 57.18,54.63 57.2,54.62 57.18,54.62 v2(57.18,54.33) ; v1(88.68,80.09) 88.63,80.14 C570.2 ; C605.1 v2(187.78,66.88) ; v2(189.18,94.25) 189.18,94.25 189.19,94.25 189.19,94.24 189.55,94.59 189.78,94.59 190.26,95.07 Q501.1 ; v2(65.67,41.2) U520.3 ; U521.3 v2(65.67,26.21) ; v2(182.8,82.25) 182.45,82.25 181.86,81.66 C548.1 ; C644.1 131.27,45.8 v2(131.7,46.23) ; C591.2 v1(93.54,72.32) ; C646.1 v2(43.07,51.8) ; C585.2 98.35,75.2 98.14,75.41 ; 95.78,89.87 96.32,90.42 C530.2 ; U518.3 v2(184.96,6.55) ; C621.2 110.45,62.23 110.85,61.84 110.85,61.75 110.99,61.6 v1(110.85,61.6) ; C535.2 84.51,90.62 ; C649.1 v2(139.76,37.59) ; C631.2 186.13,53.7 186.35,53.47 v2(186.35,52.5) ; U514.3 v2(40.31,26.97) ; v2(72.86,112.4) 72.89,112.38 C520.1 ; C508.1 C509.1 179.72,113.36 v2(179.13,112.78) ; C671.1 v2(95.5,22.73) ; C666.1 v2(174.4,1.82) ; U512.4 v2(132.76,42.63) ; U522.3 v2(15.19,6.78)
  BOTTOM w0.483: C518.1 161.8,106.22 161.8,105.16 v2(162.31,104.65)
  BOTTOM w0.508: C522.1 v2(153.1,97.28) ; MT1.1 21.36,129.5 21,129.14 ; MT1.1 25.63,125.38 25.16,124.91 ; MT1.1 29.77,129.5 30.37,128.9 ; v2(161.81,84.43) 161.83,84.43 161.83,84.68 162.03,84.87 DN505.1 ; C575.2 v2(134.51,74.5) ; v1(95.31,80.39) 95.69,80.77 C560.2 ; C647.1 v2(152.78,42.9) ; C604.1 v2(20.31,70.69) ; 3.51,115.56 3.5,115.57 MT4.1 ; DN508.1 v2(164.92,69.9) ; C532.2 v2(88.44,92.96) ; C537.2 78.56,93.22 v2(76.4,95.38) ; C625.2 v2(97.46,60.19) ; v2(72.9,85.12) 72.93,85.09 R571.1 ; R651.2 156.9,58.53 156.91,58.55 157.61,58.55 v2(157.99,58.93) ; DN503.1 158.36,128.96 158.14,128.73 v2(157.53,128.73) ; R559.2 78.47,96.61 v2(77.47,96.61) ; C529.2 v2(99.43,91.71) ; v2(54.13,22.4) 53.77,22.76 53.77,23.09 53.3,23.56 U513.3 ; R521.2 174.36,110.74 v2(175.58,110.74) ; 196.82,7.94 196.5,7.62 MT6.1 191.25,3.5 190.66,2.92 ; C525.1 v2(106.55,98.77) ; v2(158.53,84.65) 158.55,84.65 159.36,85.46 DN506.1 ; v2(48.28,57.1) 48.28,57.14 48.94,57.81 R690.2 ; R510.1 v2(176.61,123.08) ; R663.1 147.28,55.88 147.51,56.11 147.51,56.24 147.6,56.33 147.6,57.06 R661.1 148.2,58.03 v2(149.08,58.91) ; v2(120.56,56.88) 120.4,57.04 R670.2 ; R573.1 v2(50.29,87.07) ; RN500.8 v2(54.85,108.54) ; C513.2 161.49,115.75 v2(161.8,115.44) ; v2(126.02,66.94) 126.02,66.89 125.54,66.41 C612.1 ; v2(54.85,109.46) RN500.7 ; R721.2 57.12,21.04 v2(56.85,21.04) ; v2(80.99,96.67) 81.77,96.67 C536.2 ; DN502.1 161.69,126.85 161.37,127.17 v2(160.41,127.17) ; v2(65.6,37.72) 67.4,37.72 C664.1 ; v2(130.14,62.08) 130.31,62.26 C611.1 ; DN507.1 v2(153.87,80.8) ; C624.2 99.81,60.19 v2(100.22,59.78) ; U1.2 v2(15.24,122.5) ; R665.1 132.63,58.67 v2(131.82,59.48) ; C603.1 v2(20.31,75.77) ; C622.2 C621.2 ; v2(24.13,71.63) 24.48,71.63 25.29,72.44 R603.1 ; C576.2 v2(134.8,69.72) ; R562.1 v2(72.2,90.55) ; v2(22.04,107.57) 21.39,108.22 U503.3 ; MT4.1 8.23,120 8.24,119.98 ; MT4.1 3.5,124.29 3.27,124.52 ; v2(160.65,52.1) 160.65,53.4 C632.1 ; U508.1 v2(124.45,61.01) ; RN502.5 55.17,86.63 v2(54.8,87) 55.35,87.55 RN502.6 ; v2(56.63,94.33) 56.45,94.15 56.23,94.15 56.03,93.95 RN501.8 55.46,93.39 55.2,93.13 55.2,92.7 55.43,92.47 RN501.7 ; 8.19,122.3 9.59,123.7 C506.1 ; C637.2 85.21,55.68 v2(85.72,56.19) ; v2(12.77,12.86) 13.05,13.14 U523.3 ; 86.66,90.83 86.66,91.11 85.15,92.62 v2(85.15,93.04) ; C627.2 v2(94.17,60.19) ; R572.1 72.75,87.88 72.6,88.04 72.6,88.03 72.59,88.03 v2(72.49,88.14) ; R652.1 v2(154.14,53.1) ; C528.2 v2(100.6,94.18) 102.11,92.67 C527.2 ; U508.3 v2(120.38,61.01) ; C538.2 73.27,92.08 v2(71.82,92.08) ; RN501.5 55.1,90.76 v2(54.71,91.15) 55.23,91.68 RN501.6 ; RN502.8 55.89,89.12 55.43,89.12 54.92,88.61 v2(54.92,88.59) 55.23,88.59 55.45,88.37 56.01,88.37 RN502.7 ; R646.1 v2(23.88,66.99) ; C503.1 v2(18.8,129.6) ; 136.94,130.64 135.81,129.5 MT2.1 128.83,129.5 128.08,130.25 ; v2(76.8,58.73) 77.19,58.34 C638.2 ; R736.1 v2(60.44,17.5) ; v2(54.85,111.51) 54.8,111.51 54.46,111.17 RN500.5 ; 2.59,7.95 3.5,7.04 MT5.1 7.55,3.5 7.94,3.89 ; v2(54.85,110.49) 54.62,110.25 RN500.6 ; v2(125.97,55.07) 125.72,55.07 125.72,55.32 Q504.1 ; R523.1 v2(154.18,106.95) ; 84.51,90.62 83.81,91.31 v2(82.04,91.31) ; C577.2 v2(123.48,69.34) ; C670.1 v2(115.06,27.53) ; C519.1 v2(159.07,105.91) ; v2(52.78,26.52) 52.54,26.76 C654.2 ; v2(156.8,51.86) 156.8,52.17 C633.1 ; R516.2 v2(171.26,111.24) ; C635.2 v2(130.62,51.36) ; R529.1 v2(22.2,109.09) ; 192.03,128.03 192.55,127.5 MT3.1 196.5,122.88 196.18,122.57 ; R605.1 v2(18.54,72.64) ; 23.7,76.39 R604.1 v2(25.2,75.7) ; C531.2 93.87,92.45 93.87,92.29 v2(93.94,92.22) ; C511.1 v2(169.81,116.26) ; C643.1 v2(151.78,44.58) ; R617.1 v2(130.18,64.54) ; C640.1 v2(164.27,49.72) ; v2(150,111.3) 149.47,110.77 R526.1 ; C526.2 v2(104.14,95.75) ; C521.1 v2(20.84,103.96) ; U502.2 v2(17.5,114.3) ; C504.1 v2(16.64,129.6) ; U500.3 v2(16.84,122.48) ; C524.1 v2(152.39,93.22) ; C636.2 v2(91.76,59.11)
  BOTTOM w0.635: v2(169.5,2.21) 169.5,3.7 C667.1 ; C657.1 157.97,18.01 v2(158.75,18.79) ; v2(158.99,17.47) 159.3,17.78 D502.2 ; C658.1 145.26,18.01 v2(145.29,18.03) ; C656.1 170.66,18.01 v2(170.69,18.03) ; D506.2 148.36,3.71 v2(147.27,3.71) ; D507.2 v2(136.4,2.69) ; C668.1 158.6,4.04 v2(158.62,4.06) ; D504.2 v2(135.13,18.98) ; C669.1 145.38,4.38 146.37,4.38 v2(146.38,4.39) ; D503.2 v2(146.94,17.78) ; D505.2 v2(160.53,2.66)
  vias: v1(89.23,74.7) v1(89.84,73.95) v1(91.66,80.09) v1(93.9,80.83) v1(97.51,74.23) v1(97.77,78.29) v1(97.87,79.31) v1(97.94,72.08) v1(98.04,76.64) v1(98.39,80.06) v1(99.21,76.63) v2(1.27,131.72) v2(1.27,129.18) v2(1.27,126.64) v2(1.27,124.1) v2(1.27,113.94) v2(1.27,98.7) v2(1.27,96.16) v2(1.27,93.62) v2(1.27,91.08) v2(1.27,88.54) v2(1.27,86) v2(1.27,83.46) v2(1.27,80.92) v2(1.27,78.38) v2(1.27,75.84) v2(1.27,73.3) v2(1.27,70.76) v2(1.27,63.14) v2(1.27,60.6) v2(1.27,58.06) v2(1.27,55.52) v2(1.27,52.98) v2(1.27,50.44) v2(1.27,47.9) v2(1.27,45.36) v2(1.27,42.82) v2(1.27,40.28) v2(1.27,37.74) v2(1.27,35.2) v2(1.27,32.66) v2(1.27,30.12) v2(1.27,27.58) v2(1.27,25.04) v2(1.27,22.5) v2(1.27,19.96) v2(1.27,17.42) v2(1.27,14.88) v2(1.27,12.34) v2(1.27,9.8) v2(3.17,131.72) v2(5.71,131.72) v2(8.26,131.72) v2(8.19,121.79) v2(8.26,1.27) v2(10.8,131.72) v2(10.8,1.27) v2(13.34,131.72) v2(13.34,1.27) v2(15.88,131.72) v2(15.88,1.27) v2(18.41,131.72) v2(18.41,1.27) v2(20.95,131.72) v2(20.95,1.27) v2(23.49,1.27) v2(26.03,1.27) v2(28.58,1.27) v2(31.12,131.72) v2(31.12,1.27) v2(33.66,131.72) v2(33.66,1.27) v2(36.2,131.72) v2(36.2,1.27) v2(38.73,131.72) v2(38.73,1.27) v2(41.27,131.72) v2(41.27,1.27) v2(43.81,131.72) v2(43.81,1.27) v2(46.21,1.12) v2(46.36,131.72) v2(48.89,131.72) v2(48.89,1.27) v2(49.33,15.85) v2(51.44,131.72) v2(51.44,1.27) v2(53.23,13.86) v2(53.98,131.72) v2(53.98,1.27) v2(56.52,131.72) v2(56.52,1.27) v2(59.05,131.72) v2(59.05,1.27) v2(61.59,131.72) v2(61.59,1.27) v2(64.14,131.72) v2(64.14,1.27) v2(66.63,1.11) v2(66.67,131.72) v2(69.22,131.72) v2(69.22,1.08) v2(71.75,131.72) v2(71.75,1.08) v2(74.3,131.72) v2(74.3,1.27) v2(76.83,131.72) v2(76.83,1.27) v2(79.38,131.72) v2(79.38,1.27) v2(81.91,131.72) v2(81.91,1.27) v2(84.37,131.72) v2(84.45,1.27) v2(85.5,4.32) v2(87,131.72) v2(87,1.27) v2(89.53,131.72) v2(89.53,1.27) v2(90.58,11.94) v2(92.08,131.72) v2(92.08,1.27) v2(94.39,11.94) v2(94.61,131.72) v2(94.61,1.27) v2(95.66,13.21) v2(97.16,131.72) v2(97.16,1.27) v2(99.69,131.72) v2(99.69,1.27) v2(102.24,131.84) v2(102.23,1.27) v2(104.78,131.72) v2(104.8,1.27) v2(107.31,131.72) v2(107.31,1.27) v2(109.85,131.72) v2(109.85,1.27) v2(112.39,131.72) v2(112.39,1.27) v2(114.94,131.72) v2(114.93,1.27) v2(117.47,131.72) v2(117.47,1.27) v2(120.02,131.72) v2(120.02,1.27) v2(122.56,131.72) v2(122.56,1.27) v2(125.09,131.72) v2(125.09,1.27) v2(127.63,131.72) v2(127.63,1.27) v2(130.18,1.27) v2(132.72,1.27) v2(135.25,1.27) v2(137.79,131.72) v2(137.79,1.27) v2(140.34,131.72) v2(140.34,1.27) v2(140.64,68.4) v2(140.67,67.28) v2(141.44,69.67) v2(142.35,69.71) v2(142.8,65.96) v2(142.88,131.72) v2(142.88,1.27) v2(143.27,69.64) v2(145.41,131.72) v2(145.41,1.27) v2(145.65,59) v2(147.96,131.72) v2(147.96,1.27) v2(149.48,80.39) v2(150.39,80.14) v2(150.37,78.94) v2(150.5,131.72) v2(150.5,1.27) v2(153.03,131.72) v2(153.03,1.27) v2(155.57,131.72) v2(155.57,1.27) v2(157.99,62.74) v2(157.99,61.47) v2(157.99,60.2) v2(158.12,131.72) v2(158.12,1.27) v2(159.26,115.44) v2(159.26,114.17) v2(159.26,112.9) v2(159.26,111.63) v2(159.26,62.74) v2(159.26,61.47) v2(159.26,60.2) v2(159.26,58.93) v2(160.53,114.17) v2(160.53,112.9) v2(160.53,111.63) v2(160.53,61.47) v2(160.53,60.2) v2(160.66,131.72) v2(160.66,1.27) v2(160.91,80.7) v2(161.44,82.5) v2(161.8,114.17) v2(161.8,112.9) v2(161.8,62.74) v2(161.8,60.2) v2(161.8,58.93) v2(162.61,82.55) v2(162.71,41.62) v2(163.07,115.44) v2(163.07,112.9) v2(163.07,111.63) v2(163.19,131.72) v2(163.19,1.27) v2(163.99,41.46) v2(164.96,41.43) v2(165.73,131.72) v2(165.73,1.27) v2(165.96,41.43) v2(167.13,87.88) v2(168.12,87.88) v2(168.28,131.72) v2(168.28,1.27) v2(169.06,87.88) v2(169.98,87.88) v2(170.81,131.72) v2(170.81,1.27) v2(170.92,87.88) v2(171.91,87.91) v2(173.35,131.72) v2(173.35,1.27) v2(175.9,131.72) v2(175.9,97.79) v2(175.9,1.27) v2(177.16,97.79) v2(177.16,96.52) v2(178.44,131.72) v2(178.44,96.52) v2(178.44,1.27) v2(180.31,97.84) v2(180.97,131.72) v2(180.97,1.27) v2(181.31,97.84) v2(182.83,97.76) v2(183.51,131.72) v2(183.51,1.27) v2(183.87,97.82) v2(184.53,14.54) v2(184.53,12.76) v2(186.06,131.72) v2(186.06,1.27) v2(186.31,14.54) v2(188.3,49.32) v2(188.3,47.32) v2(188.3,46.32) v2(188.3,45.32) v2(188.59,131.72) v2(188.59,1.27) v2(189.3,49.32) v2(190.3,49.32) v2(191.13,131.72) v2(191.13,1.27) v2(193.68,131.72) v2(194.3,47.32) v2(194.3,46.32) v2(194.3,45.32) v2(198.58,11.84) v2(198.7,112.81) v2(198.7,99.86) v2(198.73,90.45) v2(198.73,80.29) v2(198.73,58.06) v2(198.73,55.52) v2(198.73,52.98) v2(198.73,50.44) v2(198.73,47.9) v2(198.73,45.36) v2(198.73,42.82) v2(198.73,40.28) v2(198.73,37.74) v2(198.73,35.2) v2(198.73,32.66) v2(198.73,30.12) v2(198.73,27.58) v2(198.73,25.04) v2(198.73,22.5) v2(198.68,18.14) v2(198.68,15.6) v2(198.68,13.06) v3(0.68,121.17) v3(0.68,118.83) v3(0.68,4.67) v3(0.68,2.33) v3(2.33,122.82) v3(2.33,117.18) v3(2.33,6.32) v3(2.33,0.68) v3(4.67,122.82) v3(4.67,117.18) v3(4.67,6.32) v3(4.67,0.68) v3(6.32,121.17) v3(6.32,118.83) v3(6.32,4.67) v3(6.32,2.33) v3(22.8,130.67) v3(22.81,128.33) v3(24.46,132.32) v3(24.46,126.68) v3(26.79,132.32) v3(26.79,126.68) v3(28.44,130.67) v3(28.45,128.33) v3(129.8,130.67) v3(129.81,128.33) v3(131.46,132.32) v3(131.46,126.68) v3(133.79,132.32) v3(133.79,126.68) v3(135.44,130.67) v3(135.45,128.33) v3(193.68,128.67) v3(193.68,126.33) v3(193.68,4.67) v3(193.68,2.33) v3(195.33,130.32) v3(195.33,124.68) v3(195.33,6.32) v3(195.33,0.68) v3(197.67,130.32) v3(197.67,124.68) v3(197.67,6.32) v3(197.67,0.68) v3(199.32,128.67) v3(199.32,126.33) v3(199.32,4.67) v3(199.32,2.33)
P5V: length 777
  TOP w0.203: 27.35,7.84 J54.1
  TOP w0.254: 89.49,118.98 89.78,118.98 89.99,119.04 J2.11 89.99,121.34 v2(89.75,121.58) 89.49,121.32 J2.9 89.49,118.98
  TOP w0.279: J1.9 38.37,118.98 v2(38.61,118.75) 38.87,119.01 J1.11
  TOP w0.305: 89.49,118.98 v2(89.26,118.47)
  TOP w0.381: v2(89.75,121.58) 90.11,121.94 C5.1
  TOP w0.508: 129.56,61.58 128.92,62.22 128.92,62.61 125.1,66.43 125.1,67.31 125.4,67.61 v2(125.4,67.62) ; 129.56,61.58 129.82,61.32 130.58,61.32 131.42,62.15 132.05,62.15 132.74,61.47 133.89,61.47 136.55,58.8 137.39,58.8 139.34,60.76 141.29,60.76 143.18,62.65 143.18,65.27 143.56,65.65 143.56,68.77 144.09,69.3 144.09,69.94 143.18,70.85 R27.1 143.18,75.13 TP25.1 ; 129.56,61.58 129.56,59.61 129.45,59.51 129.45,55.65 128.1,54.31 122.38,54.31 120.6,56.08 119.92,56.08 v2(118.31,57.69) ; 27.35,7.84 27.35,5.95 v2(28.13,5.17) ; v2(126.95,3.36) 126.97,3.36 126.99,3.38 126.99,8.91 128.26,10.19 128.26,15.41 125.65,18.02 v2(123.72,18.02) ; v2(69.19,44.67) 69.69,44.18 J53.1 ; v2(38.61,118.75) 38.61,122.54 C3.1
  L03_SIG1 w0.508: v2(177.86,8.89) 177.84,8.89 176.74,9.99 v2(176.74,38.62) ; 4.15,23.6 4.15,12.3 4.51,11.94 4.51,9.42 v2(4.22,9.14) ; 4.09,70.59 5.21,69.47 ; 4.09,70.59 5.61,70.59 6.11,70.08 6.11,64.37 3.79,62.05 v2(3.79,33.64) v2(3.79,32.37) 3.79,23.24 ; 4.09,70.59 4.03,70.59 ; 4.03,70.59 5.18,71.74 ; 4.03,70.59 J14.8 ; v2(118.31,57.69) v2(118.31,56.68) v2(118.31,55.66) 118.03,55.39 118.03,50.66 122.45,46.24 122.45,42.78 122.94,42.29 122.94,41.35 v2(124.08,40.21) 124.28,40.01 v2(124.28,39.22) 124.28,38.53 124.88,37.93 124.88,28.51 125.33,28.06 125.33,23.5 123.37,21.54 123.37,18.37 v2(123.72,18.02)
  L05_SIG2 w0.508: v2(124.28,39.22) 126.11,39.22 130.99,34.34 136.2,34.34 137.57,35.71 144.29,35.71 146.58,33.41 146.58,30.8 148.14,29.25 152.32,29.25 153.47,30.4 175.5,30.4 176.44,31.34 176.44,38.31 v2(176.74,38.62) 188.61,38.62 v2(189.15,39.17) ; 32,43.77 23.33,35.11 19.61,35.11 17.59,33.09 4.35,33.09 v2(3.79,33.64) ; v2(33.85,3.81) 29.77,3.81 28.41,5.17 v2(28.13,5.17) 26.58,5.17 25.86,4.45 22.34,4.45 21.31,5.49 15.52,5.49 v2(14.7,4.67) ; v2(69.19,44.67) 68.58,45.29 60.15,45.29 55.41,40.55 52.63,40.55 49.85,43.32 47.03,43.32 45.88,44.47 39.51,44.47 38.55,45.43
  BOTTOM w0.254: C672.2 33.72,3.68 v2(33.85,3.81)
  BOTTOM w0.381: R746.2 177.09,8.09 Q506.2 ; v2(35.12,3.81) 36.95,1.98 125.6,1.98 126.95,3.34 v2(126.95,3.36) ; R766.1 8.69,6.1 6.65,8.14 5.22,8.14 v2(4.22,9.14) ; R777.1 14.97,3.82 14.7,4.09 v2(14.7,4.67)
  BOTTOM w0.508: TP25.1 145.19,77.24 145.19,82.73 144.35,83.57 141.38,83.57 140.92,84.02 140.92,86.04 140.92,89.56 140.42,90.06 140.42,92.88 140.42,94.3 137.16,97.56 137.16,99.09 135.1,101.14 135.1,102.63 132.41,105.32 132.41,106.17 133.6,107.37 133.6,109.91 134.57,110.87 135.76,110.87 136.32,111.43 136.32,112.69 136.9,113.27 136.9,113.99 147.58,124.67 147.58,128.9 146.79,129.69 145.82,129.69 ; v2(4.21,10.13) 4.22,10.12 v2(4.22,9.14) ; 139.12,125.73 138.3,125.73 136.42,123.85 128.47,123.85 125.93,121.31 125.93,119.13 124.7,117.89 124.7,117.89 124.17,117.37 121.97,117.37 119.73,119.61 114,119.61 113,120.6 113,121.69 111.76,122.94 111.76,126.49 110.92,127.33 109.78,127.33 108.94,126.49 91.29,126.49 ; v2(35.12,3.81) v2(33.85,3.81) 33.85,4.45 32.58,5.72 28.68,5.72 v2(28.13,5.17) ; v2(189.15,39.17) 191.01,39.17 191.62,39.78 R698.2 ; J14.8 2.29,72.32 2.29,85.85 3.35,86.92 8.06,86.92 8.91,86.07 ; v2(128.03,3.33) 127.99,3.36 v2(126.95,3.36) ; R746.2 177.05,8.89 v2(177.86,8.89) ; 9.08,85.91 9.81,85.17 9.81,82.14 J15.8 ; 33.78,120.27 28.59,115.08 28.59,111.66 25.87,108.94 25.87,105.66 19.86,99.65 ; R618.1 124.46,66.66 125.41,67.6 125.41,67.62 v2(125.4,67.62) ; 89.69,124.73 89.66,124.75 84.29,124.75 81.81,127.22 80.91,127.22 79.28,128.85 72.52,128.85 71.42,127.75 71.42,123.61 71.75,123.27 71.75,121.79 70.42,120.46 68.48,120.46 68.19,120.74 63.62,120.74 62.38,119.5 59.18,119.5 58.31,118.63 50.8,118.63 48.69,120.74 40.6,120.74 v2(38.61,118.75)
  vias: v2(123.73,17.19) v2(140.41,91.57) v2(140.41,90.5) v2(140.77,127.43) v2(141.4,91.54) v2(141.4,90.5) v2(141.6,128.22) v2(142.35,128.97) v2(142.52,90.55) v2(142.62,127.99) v2(144.29,75.38) v2(192.68,43.15) v2(193.19,41.81) v2(194.09,42.71) v2(194.39,41.12)
